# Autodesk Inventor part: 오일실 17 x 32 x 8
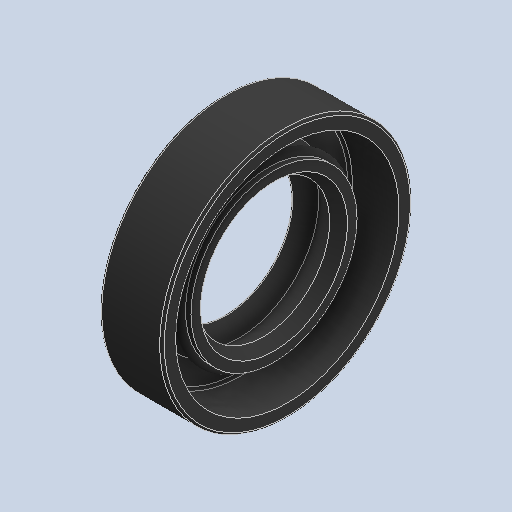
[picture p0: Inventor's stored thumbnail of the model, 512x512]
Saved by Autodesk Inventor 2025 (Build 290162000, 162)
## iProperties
Created: 2024-07
Part Number: 오일실 17 x 32 x 8
Material: 고무
Description: 오일-실
Document SubType Name: Modeling
Designer: hsj03
Density: 0.93 g/cm^3
Appearance: 기본값
Author: jhkim
Sending System: Autodesk Inventor 2025
Preprocessor: ST-DEVELOPER v20
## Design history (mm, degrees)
feature "Solid1"
node "솔리드1"
